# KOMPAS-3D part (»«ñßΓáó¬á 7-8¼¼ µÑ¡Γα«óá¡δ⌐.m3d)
File: created 10.02.2016 13:21:24, last saved 22.07.2016 16:35:03.
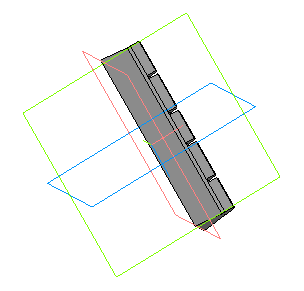
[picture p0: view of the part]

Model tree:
1. Эскиз:1
2. Операция выдавливания:1
     Расстояние 1 = 25.3; Расстояние 2 = 25.3
3. Эскиз:2
4. Вырезать элемент выдавливания:1
     Расстояние 1 = 2.5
